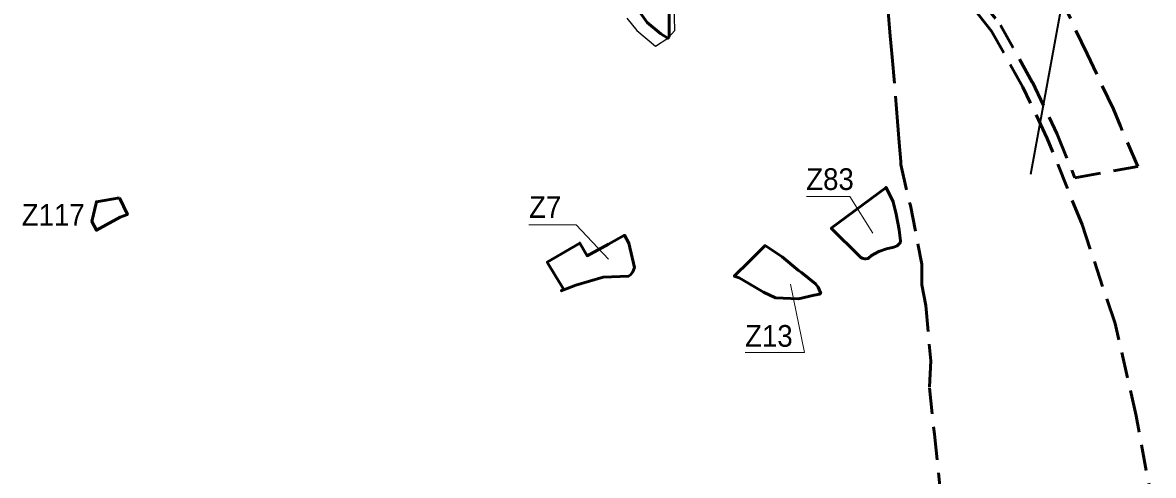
# Model space of a CAD drawing. Extents: x -650246 to -642674, y -1074280 to -1066767.
# Drawn here: x -646452 to -645202, y -1070690 to -1070188 of the extents above; entities that cross this region are included whole.
import ezdxf

# ---------------------------------------------------------------- set-up
doc = ezdxf.new("R2010")
doc.units = 0
doc.header["$LTSCALE"] = 9.6
doc.linetypes.add('MEDIUM_DASHED', pattern=[4.5, 3, -1.5])
for name, color, linetype, lineweight in [('42', 7, 'Continuous', 25), ('44', 7, 'Continuous', 53), ('45', 7, 'Continuous', 53), ('46', 7, 'Continuous', 13), ('61', 7, 'MEDIUM_DASHED', 53), ('62', 7, 'Continuous', 35)]:
    doc.layers.add(name, color=color, linetype=linetype, lineweight=lineweight)

msp = doc.modelspace()

# ---------------------------------------------------------------- linework, layer by layer
at = {"layer": '42'}
msp.add_lwpolyline([(-645784.51, -1070183.77), (-645773.48, -1070197.1), (-645752.54, -1070214.74), (-645739.12, -1070205.9), (-645731.3, -1070197.24), (-645731.94, -1070167.87)], dxfattribs=at)
at = {"layer": '44', "lineweight": 13}
msp.add_lwpolyline([(-645585.63, -1070380.811), (-645537.799, -1070380.811), (-645512.608, -1070421.471)], dxfattribs=at)
msp.add_lwpolyline([(-645585.63, -1070380.811), (-645537.799, -1070380.811), (-645512.608, -1070421.471)], dxfattribs=at)
at = {"layer": '44'}
msp.add_lwpolyline([(-645497.81, -1070370.93), (-645497.81, -1070370.93), (-645490.19, -1070386.97), (-645486.54, -1070400.38), (-645483.29, -1070417.99), (-645482.62, -1070423.93), (-645481.93, -1070430.04), (-645482.18, -1070432.13), (-645485.67, -1070435.7), (-645489.34, -1070437.05), (-645497.33, -1070438.82), (-645505.88, -1070441.74), (-645513.81, -1070446.24), (-645517.44, -1070449.23), (-645517.95, -1070449.45), (-645520.4, -1070449.87), (-645521.41, -1070449.84), (-645522.95, -1070449.61), (-645524.42, -1070449.16), (-645525.75, -1070448.41), (-645527.34, -1070447.1), (-645558.36, -1070416.1)], close=True, dxfattribs=at)
at = {"layer": '45'}
for points in [[(-645737.756, -1070204.389), (-645737.624, -1070169.544), (-645738.79, -1070156.281), (-645748.62, -1070137.889), (-645753.182, -1070121.317)], [(-645771.246, -1070175.64), (-645761.78, -1070188.29), (-645746.73, -1070201.04), (-645739.12, -1070205.9), (-645737.756, -1070204.389)]]:
    msp.add_lwpolyline(points, dxfattribs=at)
at = {"layer": '45', "lineweight": 35}
msp.add_lwpolyline([(-646344.93, -1070382.33), (-646336.25, -1070400.875), (-646344.26, -1070403.84), (-646359.769, -1070412.361), (-646370.56, -1070418.29), (-646375.63, -1070408.76), (-646370.624, -1070386.792)], close=True, dxfattribs=at)
at = {"layer": '45'}
for points in [[(-646344.93, -1070382.33), (-646336.25, -1070400.875), (-646344.26, -1070403.84), (-646359.769, -1070412.361), (-646370.56, -1070418.29), (-646375.63, -1070408.76), (-646370.624, -1070386.792)], [(-645862.66, -1070469.5), (-645853.98, -1070483.81), (-645856.87, -1070485.24), (-645840.59, -1070479), (-645810.44, -1070470.17), (-645782.57, -1070469.22), (-645780.38, -1070467.64), (-645777.8, -1070464.4), (-645776.04, -1070459.38), (-645782.13, -1070432.59), (-645786.9, -1070423.81), (-645804.58, -1070433.53), (-645828.24, -1070446.54), (-645836.32, -1070432.55), (-645872.35, -1070453.55)], [(-645862.66, -1070469.5), (-645853.98, -1070483.81), (-645856.87, -1070485.24), (-645840.59, -1070479), (-645810.44, -1070470.17), (-645782.57, -1070469.22), (-645780.38, -1070467.64), (-645777.8, -1070464.4), (-645776.04, -1070459.38), (-645782.13, -1070432.59), (-645786.9, -1070423.81), (-645804.58, -1070433.53), (-645828.24, -1070446.54), (-645836.32, -1070432.55), (-645872.35, -1070453.55)], [(-645594.769, -1070494.065), (-645577.47, -1070490.3), (-645571.13, -1070488.89), (-645569.97, -1070488.3), (-645572.86, -1070481.41), (-645575.7, -1070477.77), (-645591.49, -1070465.19), (-645594.62, -1070462.7), (-645612.77, -1070447.82), (-645631.63, -1070435.3), (-645636.42, -1070439.93), (-645648.9, -1070452.38), (-645665.6, -1070469.04), (-645660.29, -1070471.12), (-645643.4, -1070481.02), (-645633.35, -1070486.91), (-645620.22, -1070493)], [(-645594.769, -1070494.065), (-645577.47, -1070490.3), (-645571.13, -1070488.89), (-645569.97, -1070488.3), (-645572.86, -1070481.41), (-645575.7, -1070477.77), (-645591.49, -1070465.19), (-645594.62, -1070462.7), (-645612.77, -1070447.82), (-645631.63, -1070435.3), (-645636.42, -1070439.93), (-645648.9, -1070452.38), (-645665.6, -1070469.04), (-645660.29, -1070471.12), (-645643.4, -1070481.02), (-645633.35, -1070486.91), (-645620.22, -1070493)]]:
    msp.add_lwpolyline(points, close=True, dxfattribs=at)
at = {"layer": '46'}
for points in [[(-645892.796, -1070412.223), (-645840.481, -1070412.223), (-645804.515, -1070450.215)], [(-645892.796, -1070412.223), (-645840.481, -1070412.223), (-645804.515, -1070450.215)], [(-645653.64, -1070553.576), (-645587.872, -1070553.576), (-645603.567, -1070478.038)], [(-645653.64, -1070553.576), (-645587.872, -1070553.576), (-645603.567, -1070478.038)]]:
    msp.add_lwpolyline(points, dxfattribs=at)
at = {"layer": '61'}
msp.add_lwpolyline([(-645374.685, -1070012.289), (-645455.073, -1070009.111), (-645454.066, -1070125.249), (-645437.885, -1070131.669), (-645413.129, -1070146.351), (-645394.98, -1070161.51), (-645371.209, -1070191.309), (-645336.176, -1070254.367), (-645308.702, -1070311.792), (-645289.153, -1070360.302), (-645219.594, -1070347.682), (-645238.856, -1070303.185), (-645246.433, -1070284.382), (-645275.729, -1070223.153)], close=True, dxfattribs=at)
for points in [[(-645499.142, -1070133.293), (-645493.76, -1070199.15), (-645490.95, -1070226.89), (-645485.21, -1070298.03), (-645483.34, -1070321.17), (-645481.65, -1070342.07), (-645481.67, -1070345.39), (-645471, -1070391), (-645458.32, -1070455.91), (-645458.46, -1070478.86), (-645454.02, -1070501.52), (-645448.36, -1070563), (-645449.82, -1070592.72), (-645444.47, -1070643.85), (-645435.711, -1070727.497)], [(-645202.41, -1070726.571), (-645221.272, -1070623.729), (-645244.808, -1070521.357), (-645281.252, -1070412.013), (-645319.69, -1070316.63), (-645346.844, -1070259.875), (-645381.213, -1070198.011), (-645403.604, -1070169.942)]]:
    msp.add_lwpolyline(points, dxfattribs=at)
at = {"layer": '62'}
msp.add_line((-645253.165, -1069890.903), (-645338.143, -1070356.741), dxfattribs=at)

# ---------------------------------------------------------------- texts
at = {"layer": '44', "width": 0.95}
msp.add_text('Z83', height=24, dxfattribs=at).set_placement((-645586.057, -1070373.732))
msp.add_text('Z83', height=24, dxfattribs=at).set_placement((-645586.057, -1070373.732))
at = {"layer": '46', "width": 0.95}
for s, p in [('Z7', (-645892.427, -1070404.622)), ('Z7', (-645892.427, -1070404.622)), ('Z117', (-646453.122, -1070413.348)), ('Z13', (-645653.625, -1070547.221)), ('Z13', (-645653.625, -1070547.221))]:
    msp.add_text(s, height=24, dxfattribs=at).set_placement(p)

doc.saveas('drawing.dxf')
